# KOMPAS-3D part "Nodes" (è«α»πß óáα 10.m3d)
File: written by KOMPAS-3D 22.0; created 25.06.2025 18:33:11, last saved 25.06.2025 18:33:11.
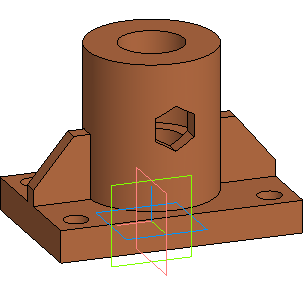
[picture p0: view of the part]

Document properties: Автор: Helen; Полное имя файла: D:\MY\WORK\MPEI\ППЭ_2025-2026\Варианты\Вар 10 СБ\Корпус вар 10.m3d

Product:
- Part/product: Nodes

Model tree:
1. Операция без истории:1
